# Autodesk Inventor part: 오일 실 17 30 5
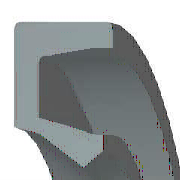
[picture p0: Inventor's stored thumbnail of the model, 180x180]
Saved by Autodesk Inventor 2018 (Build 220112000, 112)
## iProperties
IsCustomPart: 1
Created: 2012-02
Part Number: 오일 실 17 30 5
Material: 고무
Description: 오일 실 - 비스프링, 금속 케이스 GM
Document SubType Name: Modeling
Standard: JIS B 2402
Designer: mduedu
Standards Organization: JIS
Language: ko-KR
Size Designation: 17 30 5 B
Categories: <MemberInstance><Categories><Category DisplayName="샤프트 부품" InternalName="7f7aeb1f-a693-4053-b835-cee3144e0d98" Mnemonic="SHFT"><Category DisplayName="실링" Intern
Density: 0.93 g/cm^3
Appearance: Rubber-Black
Mass: 0.924459 g
Surface Area: 18.6212 cm^2
Volume: 0.994042 cm^3
Author: mduedu
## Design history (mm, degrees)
body "Solid1"
revolve "회전1" stored, may be unused: angle "d27" = 360 deg
fillet "모깎기1" dims "d28" = 0.25 (= 0.05 x b)
chamfer "모따기1" distance "d29" = 0.07143 (= 0.0142857 x b); stored, may be unused: second distance "d30" = 0.25 (= 0.05 x b), angle "d35" = 45 deg
sketch "스케치2"
  geometry: L1 (-9.367, -3.238)-(-10.233, -3.863); L2 (-8.5, -1.625)-(-9.367, -3.238); L3 (-9.15, -1)-(-8.5, -1.625); L4 (-11.317, -3.75)-(-9.15, -1); L5 (-13.075, -3.75)-(-11.317, -3.75); L6 (-14.375, -1.25)-(-13.075, -3.75); L7 (-14.375, 0)-(-14.375, -1.25); L8 (-15, 0)-(-14.375, 0); L9 (-15, -5)-(-15, 0); L10 (-11.129, -5)-(-15, -5); L11 (-10.233, -3.863)-(-11.129, -5); L12 (0, -9.6)-(0, 1.6) reference; L13 (-14, 0)-(-28, 0) reference
  constraints: 22 end point, 3 horizontal, 2 vertical, 1 parallel
  dimensions: "d2" = 5 distance of L9.start L8.start (= b); "d4" = 1 vertical distance of L8.start L3.start (= 0.2 x b); "d6" = 0.625 distance of L8.start L7.start (= 0.125 x b); "d8" = 1.25 distance of L7.start L6.start (= 0.25 x b); "d10" = 1.25 vertical distance of L5.start L9.start (= 0.25 x b); "d12" = 1.3 horizontal distance of L6.start L5.start (= 0.1 x dd - 0.1 x Diam); "d14" = 1.6129 vertical distance of L2.start L1.start (= 0.322581 x b); "d16" = 0.86667 horizontal distance of L1.start L1.end (= 0.0666667 x dd - 0.0666667 x Diam); "d18" = 0.86667 horizontal distance of L2.start L1.start (= 0.0666667 x dd - 0.0666667 x Diam); "d20" = 0.625 vertical distance of L3.start L2.start (= 0.125 x b); "d22" = 0.65 horizontal distance of L3.start L2.start (= 0.05 x dd - 0.05 x Diam); "d24" = 0.625 vertical distance of L1.start L1.end (= 0.125 x b); "d26" = 2.16667 horizontal distance of L4.start L3.start (= 0.166667 x dd - 0.166667 x Diam); "d31" = 0 distance between parallel lines of L8 L13; "d32" = 15 distance between parallel lines of L12 L9 (= 0.5 x dd); "d33" = 8.5 distance from line of L12 L2.start (= 0.5 x Diam)
other parameters: "Diam" = 17 [user parameter; used in 6 equation terms], "b" = 5 [user parameter; used in 11 equation terms], "d1" = 8 (derived), "d3" = 1.6 (derived), "d5" = 1 (derived), "d7" = 2 (derived), "d9" = 2 (derived), "d11" = 2 (derived), "d13" = 2.58065 (derived), "d15" = 1.33333 (derived), "d17" = 1.33333 (derived), "d19" = 1 (derived), "d21" = 1 (derived), "d23" = 1 (derived), "d25" = 3.33333 (derived), "d34" = 0
